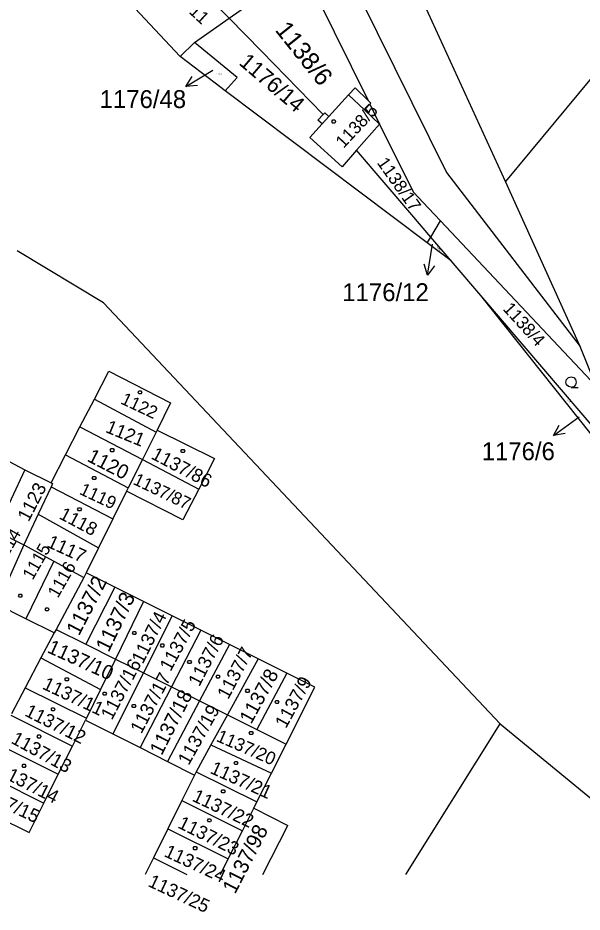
# Model space of a CAD drawing. Extents: x -621797 to -620972, y -1175539 to -1174697.
# Drawn here: x -621408.1 to -621354.5, y -1175536.4 to -1175451.4 of the extents above; entities that cross this region are included whole.
import ezdxf

# ---------------------------------------------------------------- set-up
doc = ezdxf.new("R2010")
doc.units = 0
for name, color, linetype in [('INZ mimo EON - nadz', 7, 'Continuous'), ('Rozvod plynu EON', 7, 'Continuous'), ('SDEL EON', 7, 'Continuous'), ('SDEL EON - popis', 7, 'Continuous'), ('Silnoproud EON', 7, 'Continuous'), ('Silnoproud EON - popis', 7, 'Continuous')]:
    doc.layers.add(name, color=color, linetype=linetype)

msp = doc.modelspace()

# ---------------------------------------------------------------- linework, layer by layer
at = {"layer": 'INZ mimo EON - nadz'}
for p, q in [((-621392.161, -1175457.946), (-621389.59, -1175456.4)), ((-621369.168, -1175475.893), (-621368.7, -1175472.93)), ((-621357.187, -1175491.123), (-621354.76, -1175489.36))]:
    msp.add_line(p, q, dxfattribs=at)
for points in [[(-621391.047, -1175457.859), (-621392.161, -1175457.946), (-621391.562, -1175457.002)], [(-621368.518, -1175474.984), (-621369.168, -1175475.893), (-621369.506, -1175474.828)], [(-621356.084, -1175490.94), (-621357.187, -1175491.123), (-621356.672, -1175490.131)]]:
    msp.add_lwpolyline(points, dxfattribs=at)
at = {"layer": 'Rozvod plynu EON'}
for points in [[(-621378.01, -1175461.12), (-621377.92, -1175461.27), (-621378.01, -1175461.42), (-621378.19, -1175461.42), (-621378.28, -1175461.27), (-621378.19, -1175461.12)], [(-621396.44, -1175486.87), (-621396.35, -1175487.02), (-621396.44, -1175487.17), (-621396.62, -1175487.17), (-621396.71, -1175487.02), (-621396.62, -1175486.87)], [(-621399.08, -1175492.36), (-621398.99, -1175492.51), (-621399.08, -1175492.66), (-621399.26, -1175492.66), (-621399.35, -1175492.51), (-621399.26, -1175492.36)], [(-621392.36, -1175492.45), (-621392.27, -1175492.6), (-621392.36, -1175492.75), (-621392.54, -1175492.75), (-621392.63, -1175492.6), (-621392.54, -1175492.45)], [(-621400.79, -1175495.01), (-621400.7, -1175495.16), (-621400.79, -1175495.31), (-621400.97, -1175495.31), (-621401.06, -1175495.16), (-621400.97, -1175495.01)], [(-621402.19, -1175497.99), (-621402.1, -1175498.14), (-621402.19, -1175498.29), (-621402.37, -1175498.29), (-621402.46, -1175498.14), (-621402.37, -1175497.99)], [(-621407.81, -1175506.2), (-621407.72, -1175506.35), (-621407.81, -1175506.5), (-621407.99, -1175506.5), (-621408.08, -1175506.35), (-621407.99, -1175506.2)], [(-621405.27, -1175507.5), (-621405.18, -1175507.65), (-621405.27, -1175507.8), (-621405.45, -1175507.8), (-621405.54, -1175507.65), (-621405.45, -1175507.5)], [(-621396.97, -1175509.74), (-621396.88, -1175509.89), (-621396.97, -1175510.04), (-621397.15, -1175510.04), (-621397.24, -1175509.89), (-621397.15, -1175509.74)], [(-621394.31, -1175510.94), (-621394.22, -1175511.09), (-621394.31, -1175511.24), (-621394.49, -1175511.24), (-621394.58, -1175511.09), (-621394.49, -1175510.94)], [(-621391.72, -1175512.5), (-621391.63, -1175512.65), (-621391.72, -1175512.8), (-621391.9, -1175512.8), (-621391.99, -1175512.65), (-621391.9, -1175512.5)], [(-621389.01, -1175513.89), (-621388.92, -1175514.04), (-621389.01, -1175514.19), (-621389.19, -1175514.19), (-621389.28, -1175514.04), (-621389.19, -1175513.89)], [(-621403.39, -1175514.15), (-621403.3, -1175514.3), (-621403.39, -1175514.45), (-621403.57, -1175514.45), (-621403.66, -1175514.3), (-621403.57, -1175514.15)], [(-621399.79, -1175515.51), (-621399.7, -1175515.66), (-621399.79, -1175515.81), (-621399.97, -1175515.81), (-621400.06, -1175515.66), (-621399.97, -1175515.51)], [(-621386.21, -1175515.24), (-621386.12, -1175515.39), (-621386.21, -1175515.54), (-621386.39, -1175515.54), (-621386.48, -1175515.39), (-621386.39, -1175515.24)], [(-621383.41, -1175516.31), (-621383.32, -1175516.46), (-621383.41, -1175516.61), (-621383.59, -1175516.61), (-621383.68, -1175516.46), (-621383.59, -1175516.31)], [(-621404.7, -1175517), (-621404.61, -1175517.15), (-621404.7, -1175517.3), (-621404.88, -1175517.3), (-621404.97, -1175517.15), (-621404.88, -1175517)], [(-621397.02, -1175516.68), (-621396.93, -1175516.83), (-621397.02, -1175516.98), (-621397.2, -1175516.98), (-621397.29, -1175516.83), (-621397.2, -1175516.68)], [(-621406.03, -1175519.58), (-621405.94, -1175519.73), (-621406.03, -1175519.88), (-621406.21, -1175519.88), (-621406.3, -1175519.73), (-621406.21, -1175519.58)], [(-621385.86, -1175519.26), (-621385.77, -1175519.41), (-621385.86, -1175519.56), (-621386.04, -1175519.56), (-621386.13, -1175519.41), (-621386.04, -1175519.26)], [(-621407.46, -1175522.37), (-621407.37, -1175522.52), (-621407.46, -1175522.67), (-621407.64, -1175522.67), (-621407.73, -1175522.52), (-621407.64, -1175522.37)], [(-621387.31, -1175522.11), (-621387.22, -1175522.26), (-621387.31, -1175522.41), (-621387.49, -1175522.41), (-621387.58, -1175522.26), (-621387.49, -1175522.11)], [(-621388.52, -1175524.8), (-621388.43, -1175524.95), (-621388.52, -1175525.1), (-621388.7, -1175525.1), (-621388.79, -1175524.95), (-621388.7, -1175524.8)], [(-621389.83, -1175527.56), (-621389.74, -1175527.71), (-621389.83, -1175527.86), (-621390.01, -1175527.86), (-621390.1, -1175527.71), (-621390.01, -1175527.56)], [(-621391.19, -1175530.2), (-621391.1, -1175530.35), (-621391.19, -1175530.5), (-621391.37, -1175530.5), (-621391.46, -1175530.35), (-621391.37, -1175530.2)]]:
    msp.add_lwpolyline(points, close=True, dxfattribs=at)
at = {"layer": 'SDEL EON'}
msp.add_lwpolyline([(-621355.52, -1175486.54), (-621355.775, -1175486.473), (-621355.956, -1175486.292), (-621356.022, -1175486.044), (-621355.956, -1175485.796), (-621355.775, -1175485.615), (-621355.527, -1175485.548), (-621355.279, -1175485.615), (-621355.098, -1175485.796), (-621355.031, -1175486.051), (-621355.098, -1175486.306), (-621355.279, -1175486.486), (-621355.533, -1175486.553), (-621354.863, -1175486.553)], dxfattribs=at)
at = {"layer": 'SDEL EON - popis'}
for p, q in [((-621376.68, -1175458.75), (-621375.17, -1175460.16)), ((-621374.66, -1175459.63), (-621375.17, -1175460.16)), ((-621375.17, -1175460.16), (-621373.74, -1175461.52)), ((-621379.21, -1175461.5), (-621378.57, -1175460.81))]:
    msp.add_line(p, q, dxfattribs=at)
at = {"layer": 'Silnoproud EON'}
for p, q in [((-621299.03, -1175391.16), (-621361.77, -1175466.98)), ((-621385.7, -1175428.99), (-621367.39, -1175466.13)), ((-621361.77, -1175466.98), (-621372.41, -1175443.7)), ((-621388.05, -1175451.44), (-621393.26, -1175446.12)), ((-621388.05, -1175451.44), (-621381.1, -1175446.59)), ((-621392.7, -1175455.1), (-621400.18, -1175447.11)), ((-621379.9, -1175449.03), (-621374.84, -1175459.27)), ((-621391.35, -1175453.75), (-621388.05, -1175451.44)), ((-621384.98, -1175454.58), (-621388.05, -1175451.44)), ((-621392.7, -1175455.1), (-621391.35, -1175453.75)), ((-621387.28, -1175457.1), (-621391.35, -1175453.75)), ((-621389.37, -1175457.62), (-621392.7, -1175455.1)), ((-621379.1, -1175460.59), (-621384.98, -1175454.58)), ((-621388.42, -1175458.34), (-621389.37, -1175457.62)), ((-621388.42, -1175458.34), (-621387.28, -1175457.1)), ((-621369.2, -1175472.81), (-621388.42, -1175458.34)), ((-621376.68, -1175458.75), (-621376.06, -1175458.08)), ((-621376.06, -1175458.08), (-621374.84, -1175459.27)), ((-621378.57, -1175460.81), (-621376.68, -1175458.75)), ((-621374.84, -1175459.27), (-621374.57, -1175459.53)), ((-621374.57, -1175459.53), (-621374.66, -1175459.63)), ((-621374.66, -1175459.63), (-621373.74, -1175461.52)), ((-621379.62, -1175461.13), (-621379.1, -1175460.59)), ((-621379.21, -1175461.5), (-621379.62, -1175461.13)), ((-621379.1, -1175460.59), (-621378.96, -1175460.45)), ((-621378.96, -1175460.45), (-621378.57, -1175460.81)), ((-621380.38, -1175462.78), (-621379.21, -1175461.5)), ((-621373.74, -1175461.52), (-621375.92, -1175464)), ((-621373.74, -1175461.52), (-621370.55, -1175467.95)), ((-621377.31, -1175465.59), (-621380.38, -1175462.78)), ((-621375.92, -1175464), (-621377.31, -1175465.59)), ((-621370.66, -1175470.15), (-621375.92, -1175464)), ((-621367.39, -1175466.13), (-621354.66, -1175482.66)), ((-621354.66, -1175482.66), (-621361.77, -1175466.98)), ((-621370.55, -1175467.95), (-621369.08, -1175469.51)), ((-621369.08, -1175469.51), (-621367.94, -1175470.72)), ((-621368.86, -1175472.26), (-621370.66, -1175470.15)), ((-621368.86, -1175472.26), (-621367.94, -1175470.72)), ((-621367.94, -1175470.72), (-621353.13, -1175486.42)), ((-621369.2, -1175472.81), (-621368.86, -1175472.26)), ((-621366.92, -1175474.53), (-621368.86, -1175472.26)), ((-621366.92, -1175474.53), (-621369.2, -1175472.81)), ((-621399.98, -1175478.5), (-621408.19, -1175473.58)), ((-621364.11, -1175477.82), (-621366.92, -1175474.53)), ((-621352.13, -1175492.89), (-621364.11, -1175477.82)), ((-621351.64, -1175492.41), (-621364.11, -1175477.82)), ((-621362.27, -1175518.54), (-621399.98, -1175478.5)), ((-621353.13, -1175486.42), (-621354.66, -1175482.66)), ((-621400.86, -1175487.66), (-621399.5, -1175485.02)), ((-621399.5, -1175485.02), (-621393.61, -1175488.03)), ((-621402.23, -1175490.31), (-621400.86, -1175487.66)), ((-621400.86, -1175487.66), (-621394.98, -1175490.79)), ((-621393.61, -1175488.03), (-621394.9, -1175490.63)), ((-621403.6, -1175492.96), (-621402.23, -1175490.31)), ((-621402.23, -1175490.31), (-621396.3, -1175493.41)), ((-621394.98, -1175490.79), (-621396.3, -1175493.41)), ((-621394.9, -1175490.63), (-621394.98, -1175490.79)), ((-621394.9, -1175490.63), (-621389.43, -1175493.32)), ((-621409.96, -1175493.1), (-621407.47, -1175494.37)), ((-621404.97, -1175495.63), (-621403.6, -1175492.96)), ((-621403.6, -1175492.96), (-621397.66, -1175496.09)), ((-621396.3, -1175493.41), (-621397.66, -1175496.09)), ((-621396.3, -1175493.41), (-621390.93, -1175496.22)), ((-621389.43, -1175493.32), (-621390.93, -1175496.22)), ((-621407.47, -1175494.37), (-621410.19, -1175500.19)), ((-621407.47, -1175494.37), (-621404.97, -1175495.63)), ((-621404.98, -1175496), (-621406.2, -1175498.59)), ((-621404.83, -1175495.7), (-621404.98, -1175496)), ((-621404.98, -1175496), (-621399.11, -1175499.05)), ((-621404.97, -1175495.63), (-621404.83, -1175495.7)), ((-621397.66, -1175496.09), (-621397.81, -1175496.4)), ((-621397.81, -1175496.4), (-621399.11, -1175499.05)), ((-621392.44, -1175499.13), (-621397.81, -1175496.4)), ((-621390.93, -1175496.22), (-621392.44, -1175499.13)), ((-621406.2, -1175498.59), (-621407.58, -1175501.5)), ((-621406.2, -1175498.59), (-621400.47, -1175501.81)), ((-621399.11, -1175499.05), (-621400.47, -1175501.81)), ((-621410.19, -1175500.19), (-621407.58, -1175501.5)), ((-621407.58, -1175501.5), (-621410.1, -1175507.18)), ((-621407.58, -1175501.5), (-621404.72, -1175503.06)), ((-621400.47, -1175501.81), (-621401.64, -1175504.19)), ((-621404.72, -1175503.06), (-621407.39, -1175508.54)), ((-621404.72, -1175503.06), (-621401.87, -1175504.62)), ((-621401.87, -1175504.62), (-621404.51, -1175509.55)), ((-621401.64, -1175504.19), (-621401.87, -1175504.62)), ((-621398.91, -1175505.55), (-621401.64, -1175504.19)), ((-621398.91, -1175505.55), (-621401.68, -1175510.96)), ((-621396.19, -1175506.91), (-621398.91, -1175505.55)), ((-621396.19, -1175506.91), (-621398.86, -1175512.37)), ((-621393.47, -1175508.27), (-621396.19, -1175506.91)), ((-621407.39, -1175508.54), (-621410.1, -1175507.18)), ((-621404.69, -1175509.89), (-621407.39, -1175508.54)), ((-621393.47, -1175508.27), (-621396.2, -1175513.69)), ((-621390.74, -1175509.63), (-621393.47, -1175508.27)), ((-621404.51, -1175509.55), (-621404.69, -1175509.89)), ((-621404.51, -1175509.55), (-621401.68, -1175510.96)), ((-621390.74, -1175509.63), (-621393.53, -1175515.02)), ((-621388.02, -1175510.98), (-621390.74, -1175509.63)), ((-621404.69, -1175509.89), (-621405.94, -1175512.27)), ((-621401.68, -1175510.96), (-621398.86, -1175512.37)), ((-621388.02, -1175510.98), (-621390.87, -1175516.35)), ((-621385.3, -1175512.34), (-621388.02, -1175510.98)), ((-621405.94, -1175512.27), (-621407.44, -1175515.12)), ((-621405.94, -1175512.27), (-621400.28, -1175515.27)), ((-621398.86, -1175512.37), (-621400.28, -1175515.27)), ((-621398.86, -1175512.37), (-621396.2, -1175513.69)), ((-621385.3, -1175512.34), (-621388.21, -1175517.67)), ((-621382.57, -1175513.7), (-621385.3, -1175512.34)), ((-621396.2, -1175513.69), (-621399.11, -1175519.49)), ((-621396.2, -1175513.69), (-621393.53, -1175515.02)), ((-621382.57, -1175513.7), (-621385.42, -1175519.07)), ((-621379.89, -1175515.04), (-621382.57, -1175513.7)), ((-621407.44, -1175515.12), (-621408.74, -1175517.59)), ((-621407.44, -1175515.12), (-621401.6, -1175517.98)), ((-621400.28, -1175515.27), (-621401.6, -1175517.98)), ((-621393.53, -1175515.02), (-621396.51, -1175520.79)), ((-621393.53, -1175515.02), (-621390.87, -1175516.35)), ((-621382.63, -1175520.46), (-621379.89, -1175515.04)), ((-621390.87, -1175516.35), (-621393.92, -1175522.1)), ((-621390.87, -1175516.35), (-621388.21, -1175517.67)), ((-621408.8, -1175517.71), (-621402.93, -1175520.64)), ((-621402.93, -1175520.64), (-621401.7, -1175518.18)), ((-621401.6, -1175517.98), (-621401.7, -1175518.18)), ((-621401.7, -1175518.18), (-621399.11, -1175519.49)), ((-621388.21, -1175517.67), (-621389.78, -1175520.54)), ((-621388.21, -1175517.67), (-621385.42, -1175519.07)), ((-621385.42, -1175519.07), (-621382.63, -1175520.46)), ((-621371.256, -1175532.85), (-621362.27, -1175518.54)), ((-621362.27, -1175518.54), (-621344.886, -1175532.85)), ((-621399.11, -1175519.49), (-621396.51, -1175520.79)), ((-621410.09, -1175520.44), (-621404.29, -1175523.33)), ((-621404.29, -1175523.33), (-621402.93, -1175520.64)), ((-621389.78, -1175520.54), (-621391.18, -1175523.11)), ((-621389.78, -1175520.54), (-621384.01, -1175523.21)), ((-621384.01, -1175523.21), (-621382.63, -1175520.46)), ((-621396.51, -1175520.79), (-621393.92, -1175522.1)), ((-621393.92, -1175522.1), (-621391.34, -1175523.4)), ((-621411.4, -1175523.2), (-621405.66, -1175526.06)), ((-621405.66, -1175526.06), (-621404.29, -1175523.33)), ((-621391.18, -1175523.11), (-621391.34, -1175523.4)), ((-621391.18, -1175523.11), (-621385.4, -1175525.95)), ((-621385.4, -1175525.95), (-621384.01, -1175523.21)), ((-621391.34, -1175523.4), (-621392.54, -1175525.82)), ((-621392.54, -1175525.82), (-621393.88, -1175528.51)), ((-621392.54, -1175525.82), (-621386.78, -1175528.7)), ((-621412.75, -1175526.06), (-621407.06, -1175528.85)), ((-621407.06, -1175528.85), (-621405.66, -1175526.06)), ((-621386.78, -1175528.7), (-621385.7, -1175526.55)), ((-621385.7, -1175526.55), (-621385.4, -1175525.95)), ((-621385.7, -1175526.55), (-621382.48, -1175528.19)), ((-621384.846, -1175532.85), (-621382.48, -1175528.19)), ((-621393.88, -1175528.51), (-621395.24, -1175531.26)), ((-621393.88, -1175528.51), (-621388.13, -1175531.37)), ((-621388.13, -1175531.37), (-621386.78, -1175528.7)), ((-621395.24, -1175531.26), (-621396.029, -1175532.85)), ((-621395.24, -1175531.26), (-621392.06, -1175532.85)), ((-621388.878, -1175532.85), (-621388.13, -1175531.37))]:
    msp.add_line(p, q, dxfattribs=at)

# ---------------------------------------------------------------- texts
at = {"layer": 'INZ mimo EON - nadz'}
for s, p in [('1176/48', (-621400.357, -1175459.99)), ('1176/12', (-621377.281, -1175478.35)), ('1176/6', (-621364.027, -1175493.47))]:
    msp.add_text(s, height=1.7, dxfattribs=at).set_placement(p)
at = {"layer": 'Silnoproud EON - popis'}
for s, height, rotation, p in [('1176/11', 1.2, 316.78836, (-621394.868, -1175448.15)), ('1138/6', 1.7, 308.70966, (-621383.744, -1175452.596)), ('1176/14', 1.5, 319.48127, (-621387.197, -1175455.795)), ('1138/5', 1.2, 46.81065, (-621377.17, -1175463.878)), ('1138/17', 1.2, 305.10003, (-621374.031, -1175465.197)), ('1176/12', 0.1, 310.48583, (-621368.325, -1175473.178)), ('1138/4', 1.2, 312.31929, (-621362.083, -1175479.125)), ('1122', 1.2, 334.77924, (-621398.439, -1175488.058)), ('1176/6', 0.1, 323.0909, (-621355.952, -1175487.764)), ('1121', 1.27, 337.64403, (-621399.886, -1175490.775)), ('1120', 1.36, 332.83118, (-621401.637, -1175493.512)), ('1137/86', 1.27, 332.25823, (-621395.55, -1175493.277)), ('1137/87', 1.19, 334.32087, (-621397.258, -1175495.711)), ('1123', 1.27, 62.4524, (-621407.114, -1175499.39)), ('1119', 1.2, 334.77924, (-621402.369, -1175496.658)), ('1118', 1.25, 332.14363, (-621404.303, -1175498.974)), ('1114', 1.2, 60.27516, (-621409.553, -1175503.509)), ('1117', 1.27, 335.3522, (-621405.459, -1175501.674)), ('1115', 1.2, 60.27516, (-621406.733, -1175504.939)), ('1116', 1.2, 60.27516, (-621404.333, -1175506.649)), ('1137/2', 1.45, 62.73888, (-621402.326, -1175510.239)), ('1137/3', 1.45, 64.34316, (-621399.505, -1175511.807)), ('1137/4', 1.27, 63.59831, (-621396.254, -1175512.914)), ('1137/5', 1.27, 61.65026, (-621393.611, -1175513.622)), ('1137/6', 1.27, 62.56699, (-621390.885, -1175515.06)), ('1137/10', 1.36, 335.52409, (-621405.427, -1175511.707)), ('1137/7', 1.27, 62.33781, (-621388.134, -1175516.28)), ('1137/16', 1.27, 62.33781, (-621399.194, -1175518.24)), ('1137/17', 1.27, 62.22322, (-621396.393, -1175519.55)), ('1137/8', 1.35, 61.19189, (-621385.957, -1175518.631)), ('1137/11', 1.27, 334.60735, (-621405.895, -1175515.166)), ('1137/9', 1.27, 61.19189, (-621382.649, -1175519.043)), ('1137/18', 1.36, 63.02536, (-621394.462, -1175521.604)), ('1137/12', 1.27, 333.17496, (-621407.568, -1175517.722)), ('1137/19', 1.27, 60.79082, (-621391.891, -1175522.547)), ('1137/13', 1.27, 331.34149, (-621408.863, -1175520.311)), ('1137/20', 1.22, 336.38352, (-621389.353, -1175520.144)), ('1137/14', 1.27, 332.77389, (-621410.129, -1175523.344)), ('1137/21', 1.27, 335.69597, (-621389.943, -1175523.181)), ('1137/15', 1.27, 334.66465, (-621412.007, -1175525.376)), ('1137/22', 1.27, 334.60735, (-621391.645, -1175525.826)), ('1137/23', 1.27, 333.69062, (-621393.017, -1175528.37)), ('1137/98', 1.44, 62.79618, (-621387.478, -1175534.784)), ('1137/24', 1.27, 335.06572, (-621394.314, -1175531.094)), ('1137/25', 1.27, 334.89383, (-621395.844, -1175533.934))]:
    msp.add_text(s, height=height, rotation=rotation, dxfattribs=at).set_placement(p)
msp.add_text('1176/48', height=0.1, dxfattribs=at).set_placement((-621389.247, -1175456.83))

doc.saveas('drawing.dxf')
